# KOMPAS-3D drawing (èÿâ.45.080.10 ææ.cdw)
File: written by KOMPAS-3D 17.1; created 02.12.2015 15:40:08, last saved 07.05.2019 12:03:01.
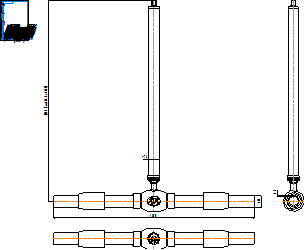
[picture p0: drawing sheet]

Sheet 1: A4, portrait

Title block, sheet 1: name: КШГ.45.080.10 СС; material: Внимание! Данный продукт является объектом авторского права ООО «Торговый Дом АДЛ». / Запрещается изменение, копирование, распространение / (в том числе путем копирования на другие сайты и ресурсы в Интернете) / или любое иное использование информации и объектов без предварительного / согласия правообладателя (ООО «Торговый Дом АДЛ»).; sheets: 1; organisation: ООО "Торговый дом АДЛ"; sheet format: A4; stored path: C:\Users\kka\KOMPAS_Work\Модели кранов для исследований\DN50\С удлинением\КШГ.32.050.40 СС ГЧ _ Шаровой кран БИВАЛ Ду50 Ру4 МПа редуцированный под приварку, с удлинением штока H=1100.cdw; drawn by: Климкович К.А.; drawn by, date: 02.12.15

Views: Вид 1, Проекционный вид 2
Referenced files in C:\Users\kka\KOMPAS_Work\Модели кранов для исследований\DN80\С удлинением\: КШТ.22.080.25 СС.a3d, КШГ.35.065.25 СС.a3d!КШГ.45.065.10 СС!Деталь (локальная).m3d
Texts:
  Klimkovich
  ADL
  (от 380 до 5000)
Dimensions and other numbers on the sheet: 1500; 90; 76; 8,2; 1:1; 1; 02.12.15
